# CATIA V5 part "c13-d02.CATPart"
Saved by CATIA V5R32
Part number: Part1
Bounding box of the stored display mesh (mm): x -33 to 33, y -200.819 to 48, z -35 to 35
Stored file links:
  D:\PROJECTS\Project 2022\CATIA V5 6R 2022\Resources\Part Files\c13_catia_v5_6r2022_prt\c13_catia_v5-6r2022_figr_13-10\c13-d02.CATPart
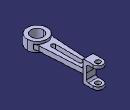
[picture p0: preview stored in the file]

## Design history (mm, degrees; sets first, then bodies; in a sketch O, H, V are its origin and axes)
Body1 (main body)
  Sketch1 on yz-plane, origin (0, 0, 0), H (0, 1, 0), V (0, 0, 1)
    line L1 (0, 0) -> (0, -35)
    point P1 (0, -35)
    line L2 (0, -35) -> (48, -35)
    point P2 (48, -35)
    line L3 (48, -35) -> (48, -25)
    point P3 (48, -25)
    line L4 (48, -25) -> (10, -25)
    point P4 (10, -25)
    line L5 (10, -25) -> (10, 0)
    point P5 (10, 0)
    point P6 (0, 0)
    point P7 (0, 0)
    point P8 (0, 35)
    point P9 (48, 35)
    point P10 (48, 25)
    point P11 (10, 25)
    point P12 (10, 0)
    point P13 (0, 0)
    line L6 (0, 0) -> (0, 35)
    line L7 (0, 35) -> (48, 35)
    line L8 (48, 35) -> (48, 25)
    line L9 (48, 25) -> (10, 25)
    line L10 (10, 25) -> (10, 0)
    length L8 = 10
    distance P3 L9 = 50
    length L2 = 48
    distance L10 L6 = 10
    vertical: L1 V, L3 V, L5 V
    horizontal: L2 H, L4 H
    symmetry: O P7 H, P1 P8 H, P2 P9 H, P3 P10 H, P4 P11 H, P5 P12 H, P6 P13 H, L1 L6 H, L2 L7 H, L3 L8 H, L4 L9 H, L5 L10 H
    coincidence: P13 P7, P12 P5, P6 P7
  Pad1: profile Sketch1, direction (1, 0, 0), length 16, mirrored extent
  Sketch2 on xy-plane, origin (0, 0, 0), H (1, 0, 0), V (0, 1, 0)
    circle A1 centre (0, -168) radius 33
    point P1 (0, -168)
    circle A2 centre (0, -168) radius 20
    distance P1 H = 168
    radius A1 = 33
    radius A2 = 20
    coincidence: P1 V
  Pad2: profile Sketch2, direction (0, 0, 1), length 16, mirrored extent
  Sketch3 on xy-plane, origin (0, 0, 0), H (1, 0, 0), V (0, 1, 0)
    line L1 (-16, 0) -> (-25, -146.4593)
    point P1 (-16, 0)
    point P2 (-25, -146.4593)
    line L2 (16, 0) -> (25, -146.4593)
    point P3 (16, 0)
    point P4 (25, -146.4593)
    reference projected line E1 (16, 48) -> (16, 0) from edge [face of Pad1 | face of Pad1]
    reference projected line E2 (-16, 48) -> (-16, 0) from edge [face of Pad1 | face of Pad1]
    projected circle E3 centre (0, -168) radius 33 from edge [face of Pad2 | face of Pad2]
    projected arc E4 centre (0, -168) radius 33 from (25, -146.4593) to (-25, -146.4593) ccw from edge [face of Pad2 | face of Pad2]
    line L3 (-16, 0) -> (16, 0)
    distance P4 P2 H = 50
    coincidence: P1 H, P3 H, P3 E1, P1 E2, P2 E3, P4 E3
    symmetry: P4 P2 V
    horizontal: L3 H
  Pad3: profile Sketch3, direction (0, 0, 1), length 8, mirrored extent
  Fillet1: radius 6, on edge [face of Pad1 | face of Pad3]; edge [face of Pad3 | face of Pad1]; edge [face of Pad1 | face of Pad1] (x2)
  Fillet2: radius 30, on edge [face of Pad3 | face of Pad2]; edge [face of Pad2 | face of Pad3]
  TritangentFillet1: Face1 face of Pad1, Face2 face of Pad1, RemoveFace face of Pad1
  TritangentFillet2: Face1 face of Pad1, Face2 face of Pad1, RemoveFace face of Pad1
  Sketch4 on face of Pad1, origin (2.8418, 32, 35), H (1, 0, 0), V (0, 1, 0)
    point P1 (-2.8418, 0)
    reference projected arc E1 centre (-2.8418, 0) radius 16 from (13.1582, 0) to (-18.8418, 0) ccw from edge [face of Pad1 | face of TritangentFillet1]
    concentricity: P1 E1
  Hole1: placed by Sketch4, at (0, 32, 35) direction (0, 0, -1), diameter 16, through (limit type 3)
  Sketch5 on face of Pad3, origin (0, 0, 8), H (1, 0, 0), V (0, 1, 0)
    construction line L1 (0, -25) -> (0, -115)
    point P1 (0, -25)
    line L2 (7, -25) -> (7, -115)
    line L3 (-7, -115) -> (-7, -25)
    arc A1 centre (0, -115) radius 7 from (7, -115) to (-7, -115) cw
    arc A2 centre (0, -25) radius 7 from (-7, -25) to (7, -25) cw
    distance P1 H = 25
    length L1 = 90
    radius A1 = 7
    coincidence: P1 V
    vertical: L1 V
    tangency: A1 L2, A2 L2, A1 L3, A2 L3
    parallelism: L1 L2
  Pocket1: profile Sketch5, direction (0, 0, -1), through (limit type 3)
